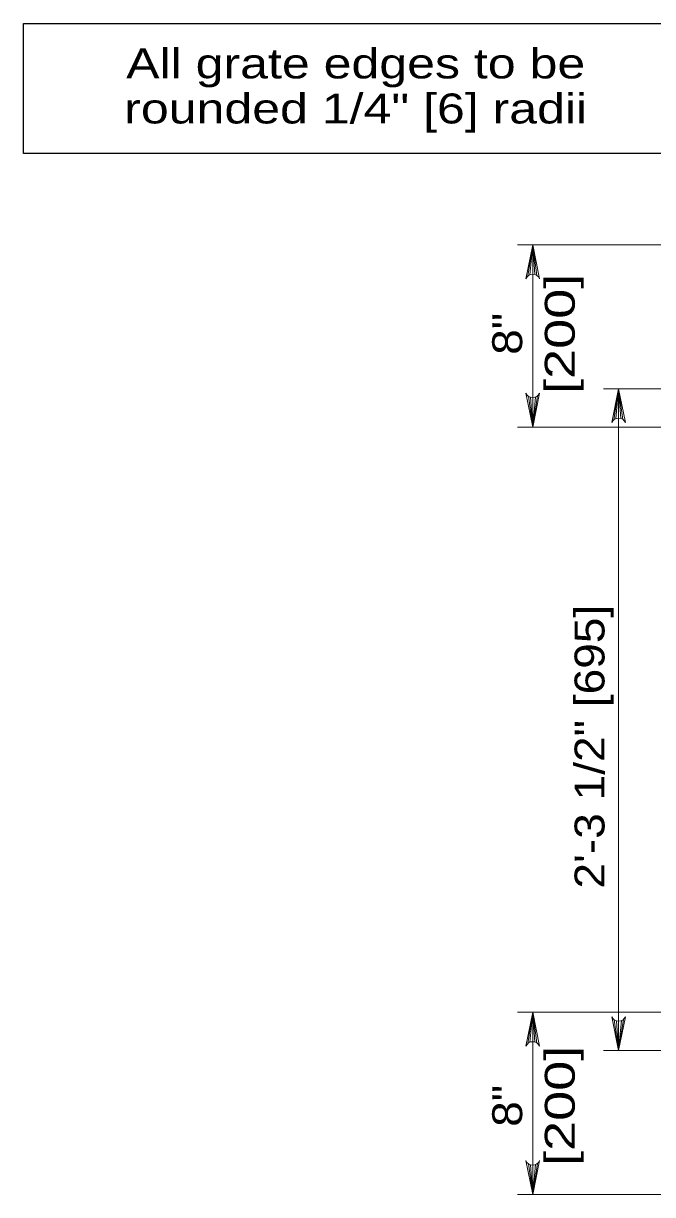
# Model space of a CAD drawing. Extents: x -410.5 to -376.5, y 1617.6 to 1661.6.
# Drawn here: x -398.78 to -395.5, y 1643.41 to 1649.51 of the extents above; entities that cross this region are included whole.
import ezdxf
from ezdxf.enums import TextEntityAlignment as Align

# ---------------------------------------------------------------- set-up
doc = ezdxf.new("R2010")
doc.units = 0
doc.header["$LTSCALE"] = 0.062
doc.layers.add('1', color=7, linetype='Continuous', lineweight=13)

msp = doc.modelspace()

# ---------------------------------------------------------------- linework, layer by layer
at = {"layer": '1'}
for p, q in [((-394.85592, 1648.3615), (-396.20775, 1648.3615)), ((-396.15392, 1648.19942), (-396.12908, 1648.3615)), ((-396.1435, 1648.2055), (-396.12908, 1648.3615)), ((-396.12908, 1648.3615), (-396.12908, 1647.41208)), ((-396.12908, 1648.20833), (-396.12908, 1648.3615)), ((-396.11775, 1648.20667), (-396.12908, 1648.3615)), ((-396.10667, 1648.20125), (-396.12908, 1648.3615)), ((-394.16367, 1647.61192), (-395.76017, 1647.61192)), ((-395.70633, 1647.44983), (-395.6815, 1647.61192)), ((-395.69592, 1647.45592), (-395.6815, 1647.61192)), ((-395.6815, 1647.45875), (-395.6815, 1647.61192)), ((-395.67017, 1647.45717), (-395.6815, 1647.61192)), ((-395.65908, 1647.45167), (-395.6815, 1647.61192)), ((-396.1515, 1647.57233), (-396.12908, 1647.41208)), ((-396.14042, 1647.56692), (-396.12908, 1647.41208)), ((-396.10433, 1647.57417), (-396.12908, 1647.41208)), ((-396.11475, 1647.56808), (-396.12908, 1647.41208)), ((-396.12908, 1647.56525), (-396.12908, 1647.41208)), ((-394.85592, 1647.41208), (-396.20775, 1647.41208)), ((-394.85592, 1644.36383), (-396.20775, 1644.36383)), ((-396.15392, 1644.20175), (-396.12908, 1644.36383)), ((-396.1435, 1644.20783), (-396.12908, 1644.36383)), ((-396.12908, 1644.21067), (-396.12908, 1644.36383)), ((-396.11775, 1644.209), (-396.12908, 1644.36383)), ((-396.10667, 1644.20358), (-396.12908, 1644.36383)), ((-396.12908, 1644.36383), (-396.12908, 1643.41433)), ((-395.70392, 1644.32417), (-395.6815, 1644.16392)), ((-395.69283, 1644.31875), (-395.6815, 1644.16392)), ((-395.65675, 1644.32608), (-395.6815, 1644.16392)), ((-395.66717, 1644.31992), (-395.6815, 1644.16392)), ((-395.6815, 1644.31708), (-395.6815, 1644.16392)), ((-394.16367, 1644.16392), (-395.76017, 1644.16392)), ((-396.1515, 1643.57458), (-396.12908, 1643.41433)), ((-396.14042, 1643.56917), (-396.12908, 1643.41433)), ((-396.10433, 1643.5765), (-396.12908, 1643.41433)), ((-396.11475, 1643.57033), (-396.12908, 1643.41433)), ((-396.12908, 1643.5675), (-396.12908, 1643.41433)), ((-394.85592, 1643.41433), (-396.20775, 1643.41433))]:
    msp.add_line(p, q, dxfattribs=at)
at = {"layer": '1', "lineweight": 25}
msp.add_lwpolyline([(-398.78267, 1649.51433), (-395.28533, 1649.51433), (-395.28533, 1648.83658), (-398.78267, 1648.83658)], close=True, dxfattribs=at)
at = {"layer": '1'}
for points in [[(-396.1645, 1648.1845), (-396.12908, 1648.3615), (-396.09375, 1648.1845)], [(-395.71692, 1647.43492), (-395.6815, 1647.61192), (-395.64608, 1647.43492)], [(-395.6815, 1647.61192), (-395.6815, 1645.4975), (-395.6815, 1644.16392)], [(-396.09375, 1647.58908), (-396.12908, 1647.41208), (-396.1645, 1647.58908)], [(-396.1645, 1644.18683), (-396.12908, 1644.36383), (-396.09375, 1644.18683)], [(-395.64608, 1644.34092), (-395.6815, 1644.16392), (-395.71692, 1644.34092)], [(-396.09375, 1643.59133), (-396.12908, 1643.41433), (-396.1645, 1643.59133)]]:
    msp.add_lwpolyline(points, dxfattribs=at)
for centre, start, end in [((-396.12907, 1648.17022), 22.08782, 157.91395), ((-396.12915, 1647.60336), 202.08782, 337.91395), ((-395.68149, 1647.42065), 22.08782, 157.91395), ((-395.68156, 1644.35523), 202.08782, 337.91395), ((-396.12907, 1644.17255), 22.08782, 157.91395), ((-396.12915, 1643.60566), 202.08782, 337.91395)]:
    msp.add_arc(centre, 0.0382, start, end, dxfattribs=at)

# ---------------------------------------------------------------- texts
at = {"layer": '1', "width": 1.25}
for s, p in [('All grate edges to be', (-397.05133, 1649.22792)), ('rounded 1/4" [6] radii', (-397.05129, 1648.99325))]:
    msp.add_text(s, height=0.156, dxfattribs=at).set_placement(p, align=Align.CENTER)
at = {"layer": '1'}
for s, width, p in [('[200]', 1.35, (-395.90992, 1647.89758)), ('8"', 1.15, (-396.18392, 1647.89758)), ('[200]', 1.35, (-395.90992, 1643.87658)), ('8"', 1.15, (-396.18392, 1643.87658))]:
    msp.add_text(s, height=0.156, rotation=90, dxfattribs=dict(at, width=width)).set_placement(p, align=Align.CENTER)
at = {"layer": '1', "width": 1.15}
msp.add_text('2\'-3 1/2" [695]', height=0.156, rotation=90, dxfattribs=at).set_placement((-395.75492, 1645.00833))

doc.saveas('drawing.dxf')
